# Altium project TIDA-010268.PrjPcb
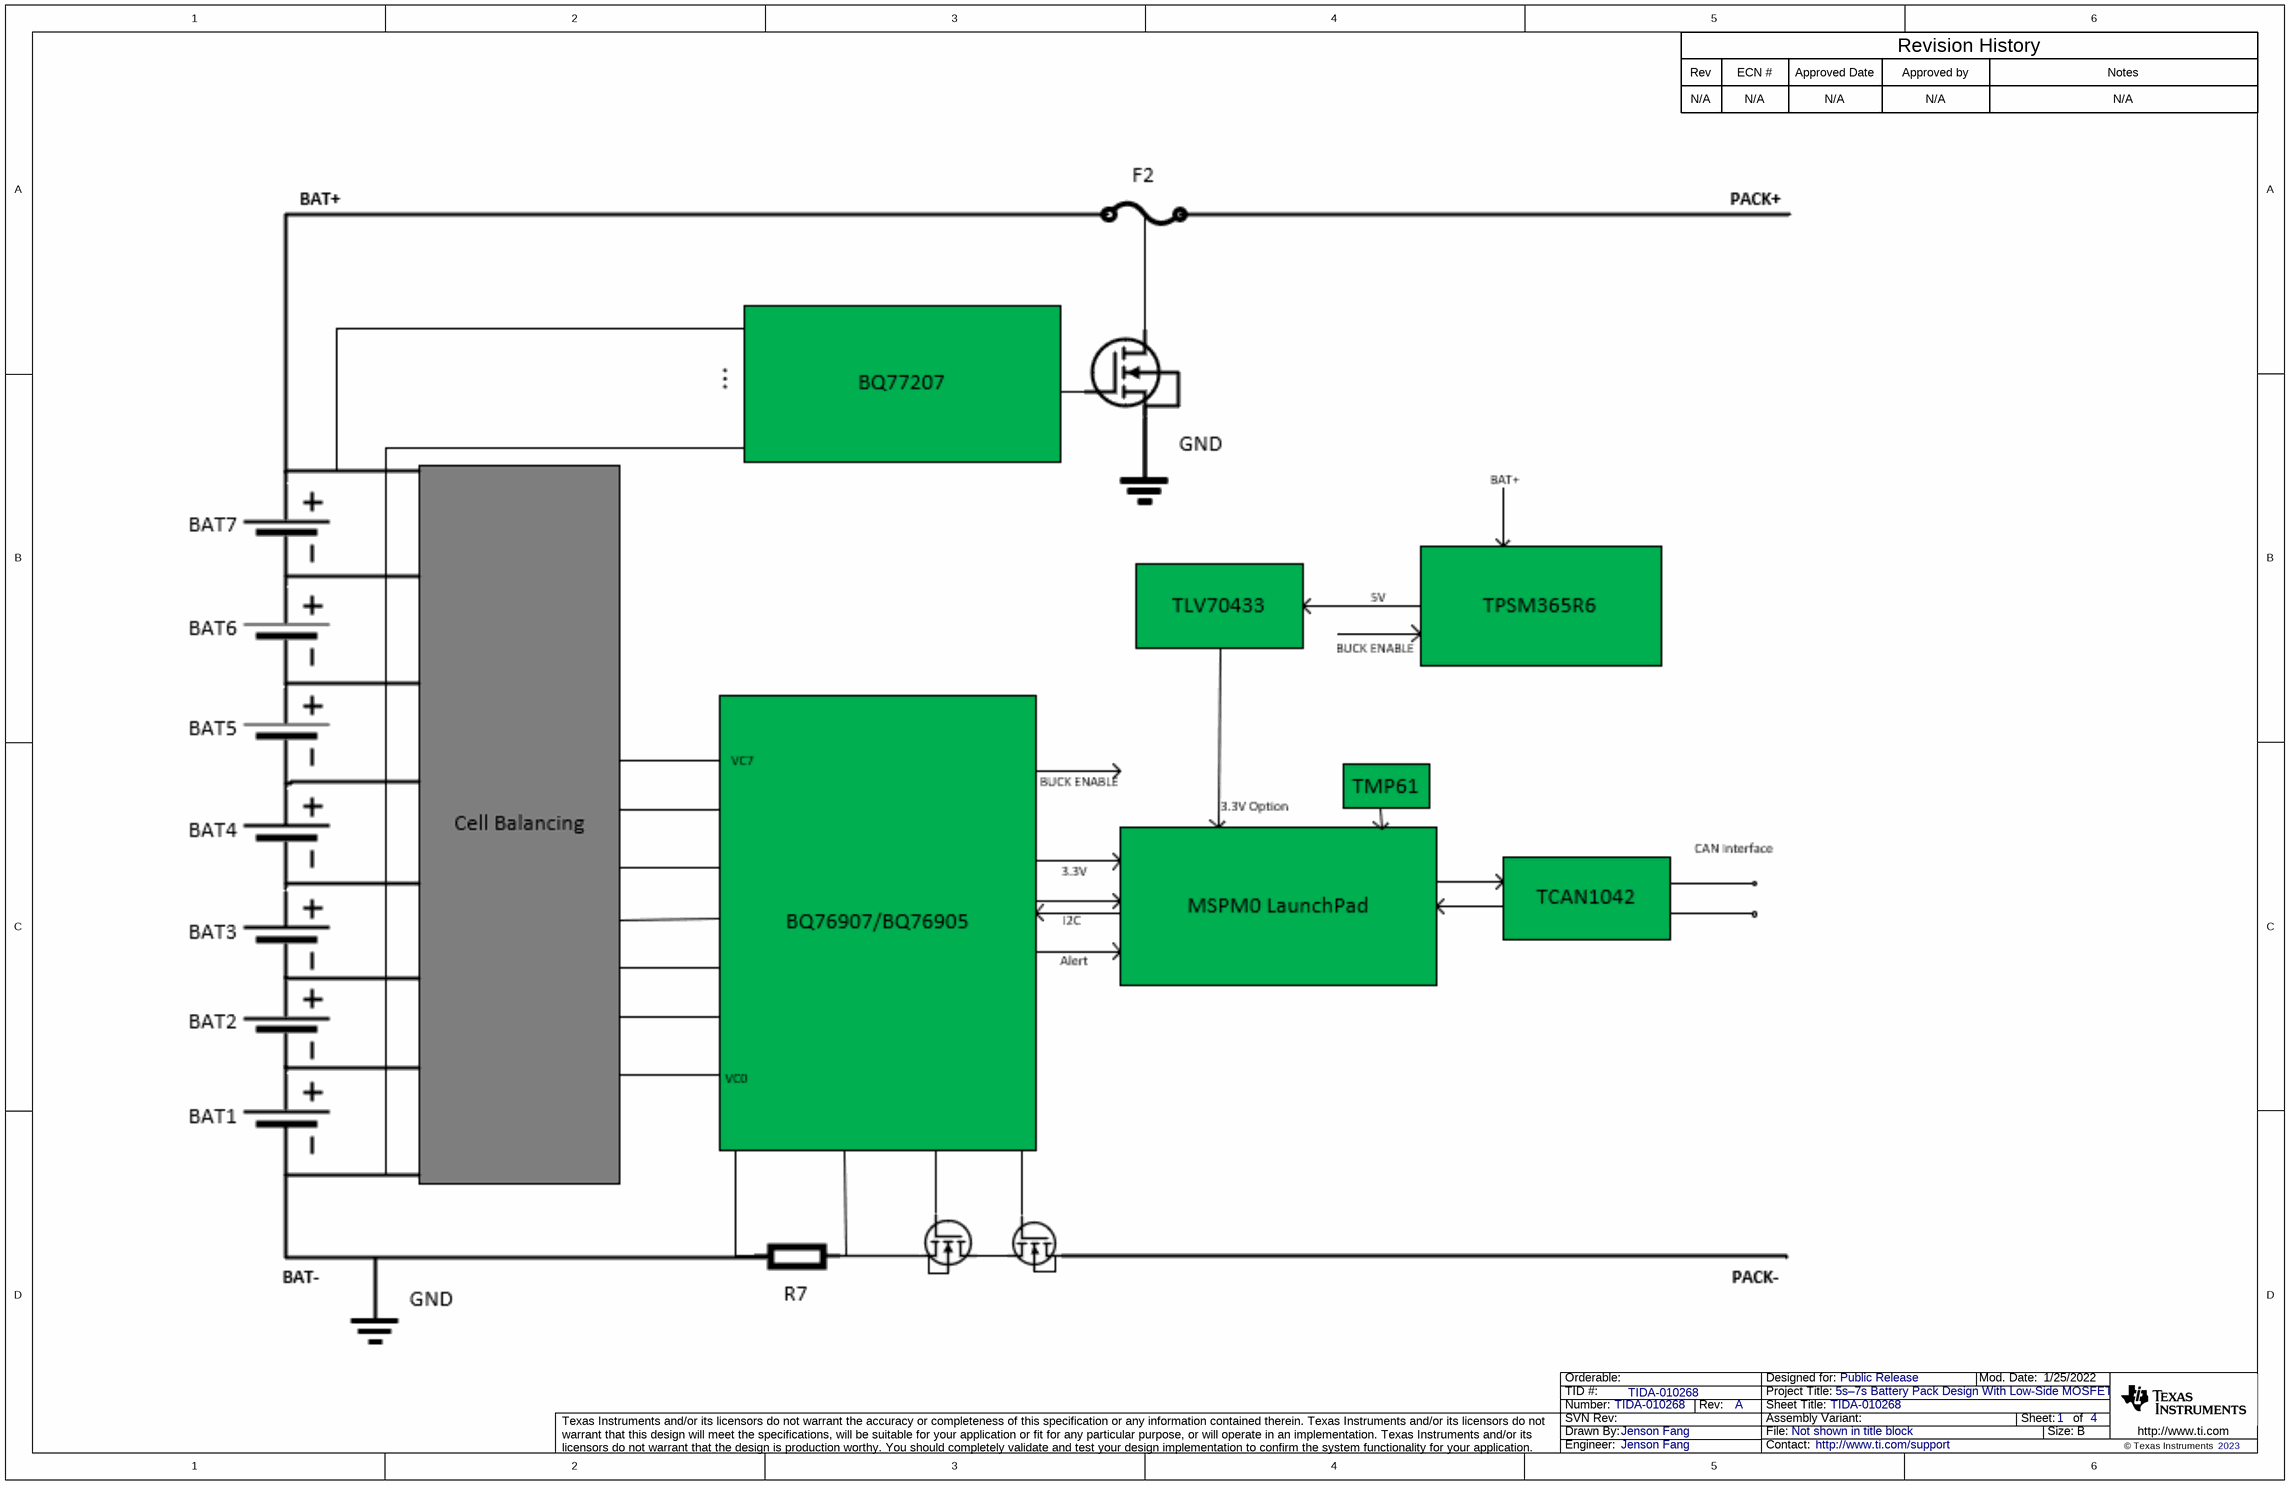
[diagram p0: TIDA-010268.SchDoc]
CopyrightYear: 2023; PCB_Layout: Jenson Fang; PCB_Rev: A; PRJ_Customer: Public Release; PRJ_Engineer: Jenson Fang; PRJ_Number: TIDA-010268; PRJ_Title: 5s–7s Battery Pack Design With Low-Side MOSFET Control; SCH_Rev: A; TechSupport: http://www.ti.com/support; TID: TIDA-010268
4 sheets, 155 parts. Net scope: global (net labels, ports and power ports of the same name join across sheets).
Board file: TIDA-010268.PcbDoc
Sheets:
  TIDA-010268.SchDoc
  TIDA-010268_Monitor and CB.SchDoc
  TIDA-010268_Power Rail.SchDoc
  TIDA-010268_Hardware.SchDoc

## Sheet TIDA-010268.SchDoc: TIDA-010268
size 431 x 279 mm; Date: Not shown in title block; ApprovedBy: Not shown in title block; CheckedBy: Not shown in title block; Author: Jenson Fang; CompanyName: Not shown in title block; DrawnBy: Jenson Fang; Engineer: Jenson Fang; Organization: Not shown in title block; Address1: Not shown in title block; Address2: Not shown in title block; Address3: Not shown in title block; Address4: Not shown in title block; DocumentNumber: 1; Revision: Use project parameter SCH_Rev; SheetNumber: 1; SheetTotal: 4; PageSetup: Record=PageOptions¦CenterHorizontal=True¦CenterVertical=True¦PrintScale=1.00¦XCorrection=1.00¦YCorrection=1.00¦PrintKind=0¦BorderSize=5000000¦LeftOffset=0¦BottomOffset=0¦Orientation=2¦PaperLength=1000¦PaperWidth=1000¦Scale=100¦PaperSource=15¦PrintQuality=600¦MediaType=1¦DitherType=10¦PaperKind=Letter¦PrintScaleMode=1

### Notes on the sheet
- Rev
- N/A
- ECN #
- Approved Date
- Approved by
- Revision History
- Notes

## Sheet TIDA-010268_Monitor and CB.SchDoc: TIDA-010268
size 431 x 279 mm; Date: Not shown in title block; ApprovedBy: Not shown in title block; CheckedBy: Not shown in title block; Author: Jenson Fang; CompanyName: Not shown in title block; DrawnBy: Jenson Fang; Engineer: Jenson Fang; Organization: Not shown in title block; Address1: Not shown in title block; Address2: Not shown in title block; Address3: Not shown in title block; Address4: Not shown in title block; DocumentNumber: 2; Revision: Use project parameter SCH_Rev; SheetNumber: 2; SheetTotal: 4; PageSetup: Record=PageOptions¦CenterHorizontal=True¦CenterVertical=True¦PrintScale=1.00¦XCorrection=1.00¦YCorrection=1.00¦PrintKind=0¦BorderSize=5000000¦LeftOffset=0¦BottomOffset=0¦Orientation=2¦PaperLength=1000¦PaperWidth=1000¦Scale=100¦PaperSource=15¦PrintQuality=600¦MediaType=1¦DitherType=10¦PaperKind=Letter¦PrintScaleMode=1
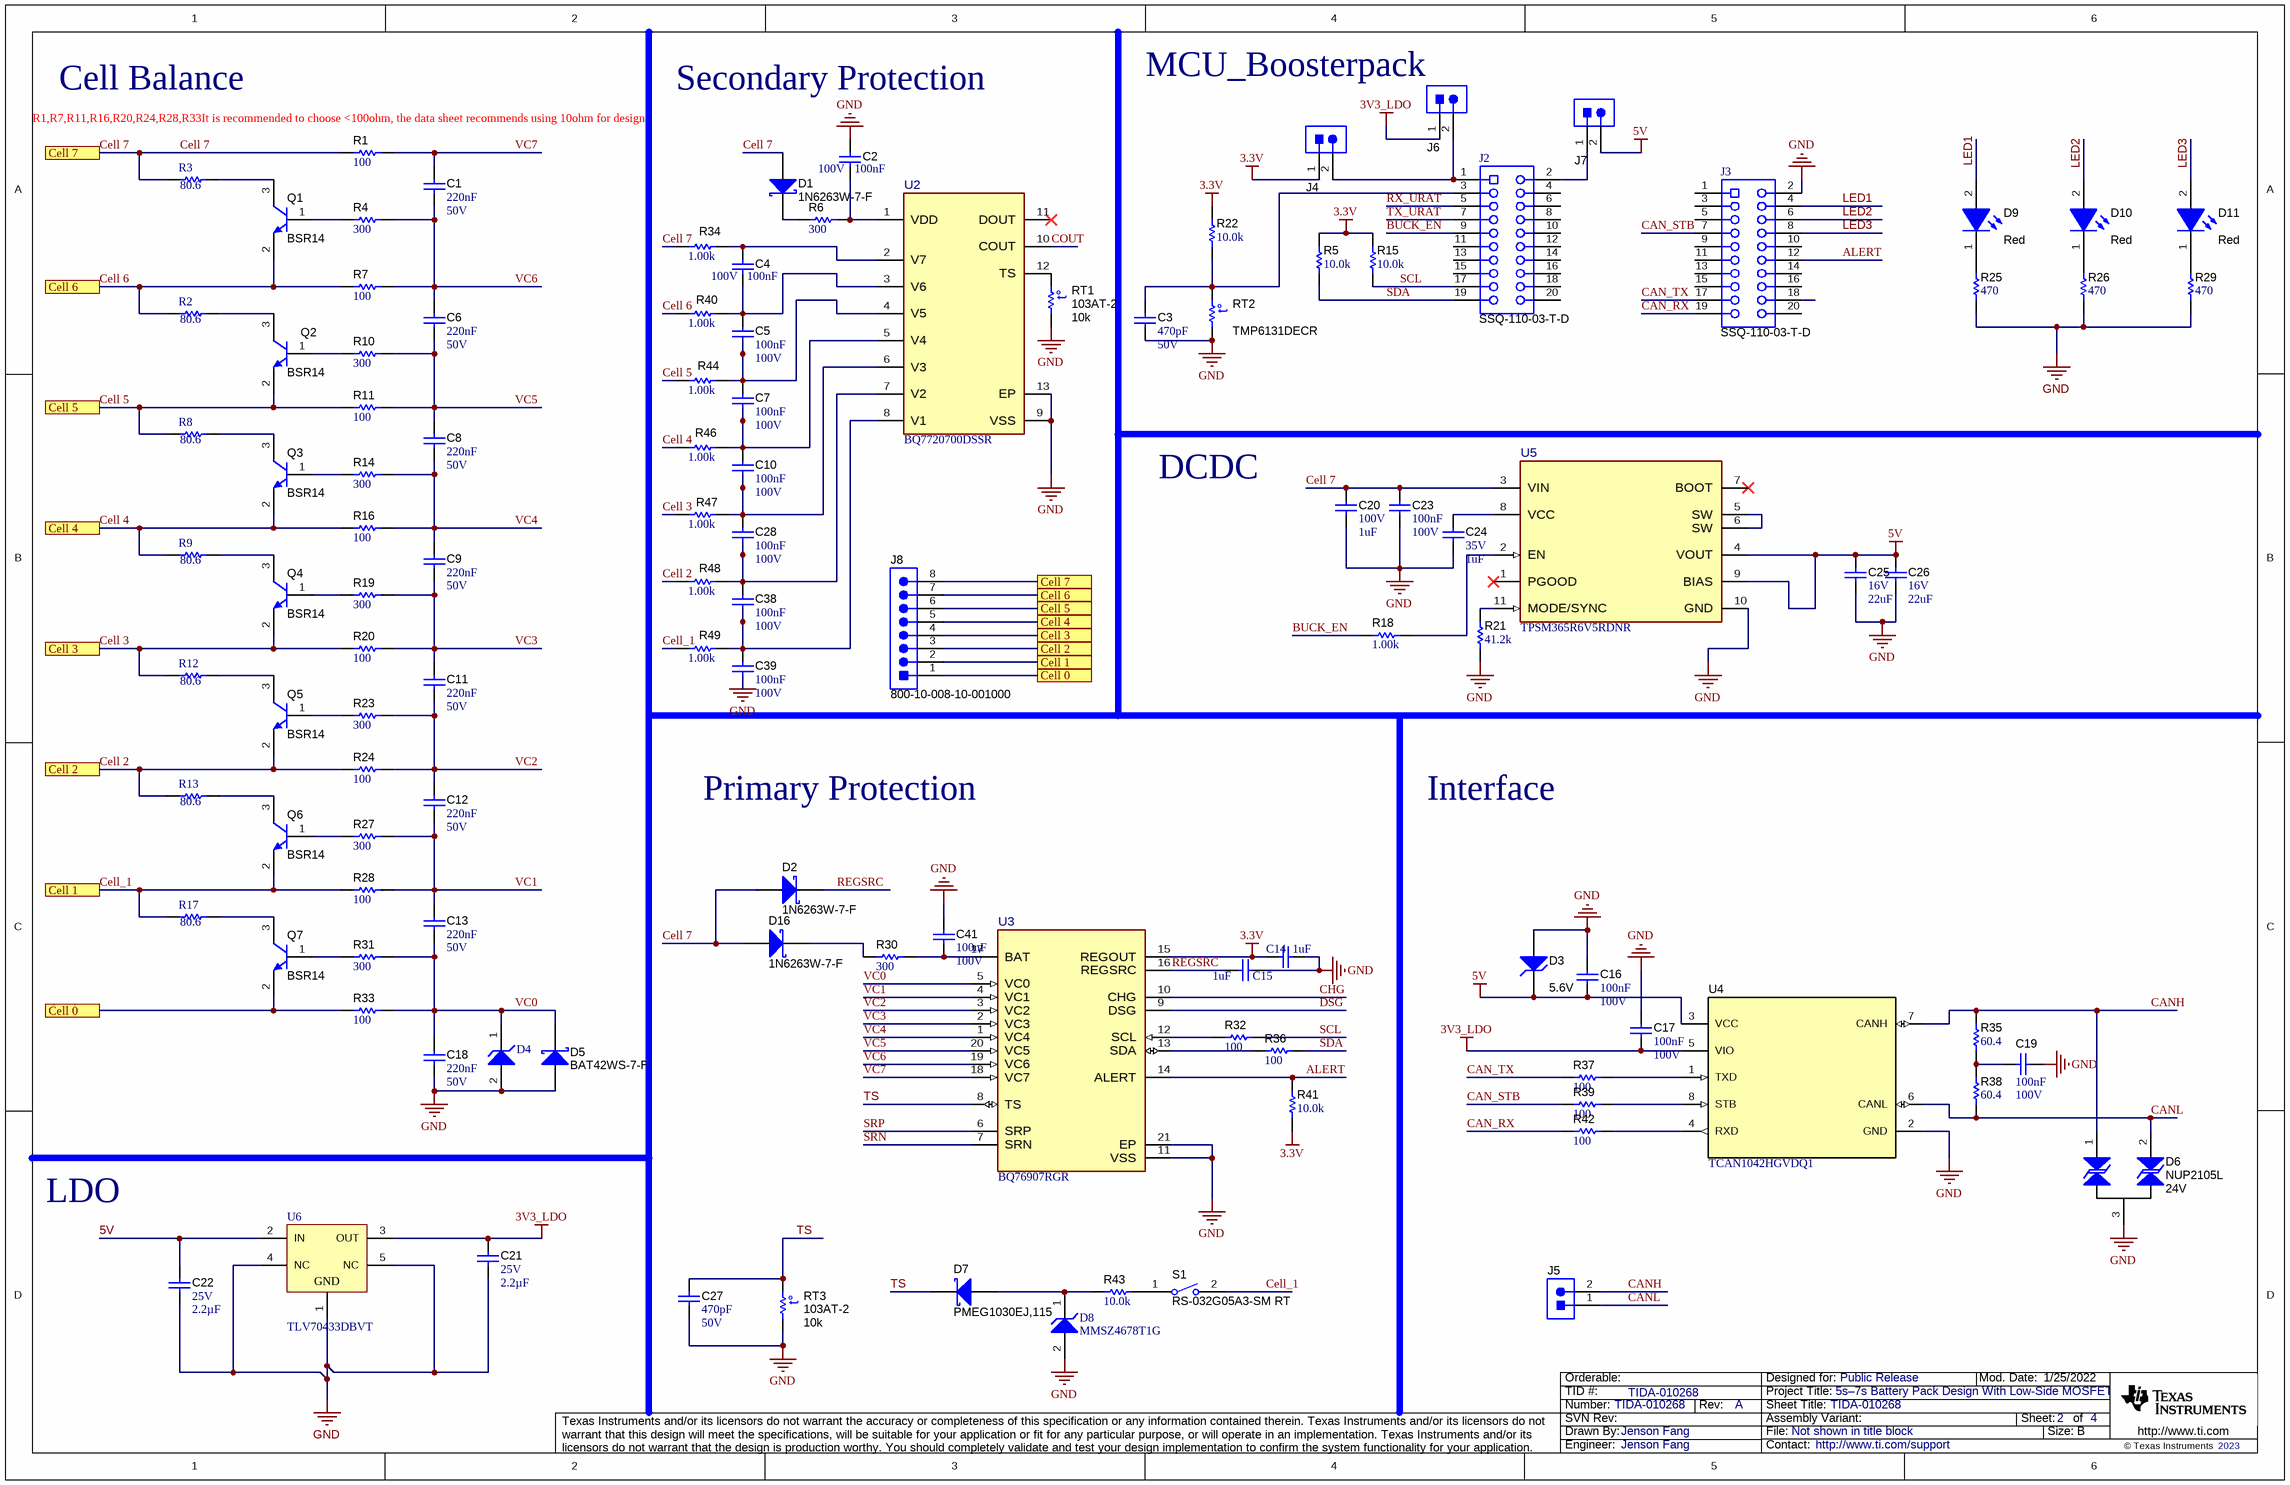
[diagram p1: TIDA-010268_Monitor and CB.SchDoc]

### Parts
C1  Cap_F: 220nF  VDC_V: 50V  [0603]  (hidden comment: GRM188R71H224KAC4D)
C2  Cap_F: 100nF  VDC_V: 100V  [0603]  (hidden comment: GRM188R72A104KA35J)
C3  Cap_F: 470pF  VDC_V: 50V  [0603]  (hidden comment: GRM188R71H471KA01D)
C4  Cap_F: 100nF  VDC_V: 100V  [0603]  (hidden comment: GRM188R72A104KA35J)
C5  Cap_F: 100nF  VDC_V: 100V  [0603]  (hidden comment: GRM188R72A104KA35J)
C6  Cap_F: 220nF  VDC_V: 50V  [0603]  (hidden comment: GRM188R71H224KAC4D)
C7  Cap_F: 100nF  VDC_V: 100V  [0603]  (hidden comment: GRM188R72A104KA35J)
C8  Cap_F: 220nF  VDC_V: 50V  [0603]  (hidden comment: GRM188R71H224KAC4D)
C9  Cap_F: 220nF  VDC_V: 50V  [0603]  (hidden comment: GRM188R71H224KAC4D)
C10  Cap_F: 100nF  VDC_V: 100V  [0603]  (hidden comment: GRM188R72A104KA35J)
C11  Cap_F: 220nF  VDC_V: 50V  [0603]  (hidden comment: GRM188R71H224KAC4D)
C12  Cap_F: 220nF  VDC_V: 50V  [0603]  (hidden comment: GRM188R71H224KAC4D)
C13  Cap_F: 220nF  VDC_V: 50V  [0603]  (hidden comment: GRM188R71H224KAC4D)
C14  value 1uF  [CAPC1608X90X35LL10T15]  (hidden comment: GRM188R61E105KA12D)
C15  value 1uF  [CAPC1608X90X35LL10T15]  (hidden comment: GRM188R61E105KA12D)
C16  Cap_F: 100nF  VDC_V: 100V  [0603]  (hidden comment: GRM188R72A104KA35J)
C17  Cap_F: 100nF  VDC_V: 100V  [0603]  (hidden comment: GRM188R72A104KA35J)
C18  Cap_F: 220nF  VDC_V: 50V  [0603]  (hidden comment: GRM188R71H224KAC4D)
C19  Cap_F: 100nF  VDC_V: 100V  [0603]  (hidden comment: GRM188R72A104KA35J)
C20  VDC_V: 100V  ValueDisplayed: 1uF  [1210_180]  (hidden comment: GRM32CR72A105KA35L)
C21  VDC_V: 25V  ValueDisplayed: 2.2µF  [0603]  (hidden comment: GRM188C71E225KE11D)
C22  VDC_V: 25V  ValueDisplayed: 2.2µF  [0603]  (hidden comment: GRM188C71E225KE11D)
C23  Cap_F: 100nF  VDC_V: 100V  [0603]  (hidden comment: GRM188R72A104KA35J)
C24  VDC_V: 35V  ValueDisplayed: 1uF  [0402]  (hidden comment: GRM155R6YA105KE11D)
C25  VDC_V: 16V  ValueDisplayed: 22uF  [0805_HV]  (hidden comment: GRM21BC81C226ME44L)
C26  VDC_V: 16V  ValueDisplayed: 22uF  [0805_HV]  (hidden comment: GRM21BC81C226ME44L)
C27  Cap_F: 470pF  VDC_V: 50V  [0603]  (hidden comment: GRM188R71H471KA01D)
C28  Cap_F: 100nF  VDC_V: 100V  [0603]  (hidden comment: GRM188R72A104KA35J)
C38  Cap_F: 100nF  VDC_V: 100V  [0603]  (hidden comment: GRM188R72A104KA35J)
C39  Cap_F: 100nF  VDC_V: 100V  [0603]  (hidden comment: GRM188R72A104KA35J)
C41  Cap_F: 100nF  VDC_V: 100V  [0603]  (hidden comment: GRM188R72A104KA35J)
D1  1N6263W-7-F  [SOD-123]
D2  1N6263W-7-F  [SOD-123]
D3  value 5.6V  [SOD-123]  (hidden comment: MMSZ4690T1G)
D4  MMSZ4685T1G  [ONSC-SOD-123-2-425-04_V]  (value not drawn)
D5  BAT42WS-7-F  [SOD-323]
D6  NUP2105L  value 24V  [SOT-23]
D7  PMEG1030EJ,115  [SOD-323F]
D8  MMSZ4678T1G  [ONSC-SOD-123-2-425-04_V]
D9  value Red  [WL_SMCW_RED_1206]  (hidden comment: 150120RS75000)
D10  value Red  [WL_SMCW_RED_1206]  (hidden comment: 150120RS75000)
D11  value Red  [WL_SMCW_RED_1206]  (hidden comment: 150120RS75000)
D16  1N6263W-7-F  [SOD-123]
J2  SSQ-110-03-T-D  [Samtec_SSQ-110-03-x-D]
J3  SSQ-110-03-T-D  [Samtec_SSQ-110-03-x-D]
J4  61300211121  [WURTH_61300211121]  (value not drawn)
J5  61300211121  [WURTH_61300211121]  (value not drawn)
J6  61300211121  [WURTH_61300211121]  (value not drawn)
J7  61300211121  [WURTH_61300211121]  (value not drawn)
J8  800-10-008-10-001000  [Mill-Max_800-10-008-10-001000]
Q1  BSR14  [SOT-23]
Q2  BSR14  [SOT-23]
Q3  BSR14  [SOT-23]
Q4  BSR14  [SOT-23]
Q5  BSR14  [SOT-23]
Q6  BSR14  [SOT-23]
Q7  BSR14  [SOT-23]
R1  ValueDisplayed: 100  [0603]  (hidden comment: CRCW0603100RFKEA)
R2  vaule: 80.6  [RESC3216X60X45LL10T20]  (hidden comment: CRCW120680R6FKEA)
R3  vaule: 80.6  [RESC3216X60X45LL10T20]  (hidden comment: CRCW120680R6FKEA)
R4  ValueDisplayed: 300  [0603]  (hidden comment: CRCW0603300RJNEA)
R5  ValueDisplayed: 10.0k  [0603]  (hidden comment: CRCW060310K0FKEA)
R6  ValueDisplayed: 300  [0603]  (hidden comment: CRCW0603300RJNEA)
R7  ValueDisplayed: 100  [0603]  (hidden comment: CRCW0603100RFKEA)
R8  vaule: 80.6  [RESC3216X60X45LL10T20]  (hidden comment: CRCW120680R6FKEA)
R9  vaule: 80.6  [RESC3216X60X45LL10T20]  (hidden comment: CRCW120680R6FKEA)
R10  ValueDisplayed: 300  [0603]  (hidden comment: CRCW0603300RJNEA)
R11  ValueDisplayed: 100  [0603]  (hidden comment: CRCW0603100RFKEA)
R12  vaule: 80.6  [RESC3216X60X45LL10T20]  (hidden comment: CRCW120680R6FKEA)
R13  vaule: 80.6  [RESC3216X60X45LL10T20]  (hidden comment: CRCW120680R6FKEA)
R14  ValueDisplayed: 300  [0603]  (hidden comment: CRCW0603300RJNEA)
R15  ValueDisplayed: 10.0k  [0603]  (hidden comment: CRCW060310K0FKEA)
R16  ValueDisplayed: 100  [0603]  (hidden comment: CRCW0603100RFKEA)
R17  vaule: 80.6  [RESC3216X60X45LL10T20]  (hidden comment: CRCW120680R6FKEA)
R18  ValueDisplayed: 1.00k  [0603]  (hidden comment: CRCW06031K00FKEA)
R19  ValueDisplayed: 300  [0603]  (hidden comment: CRCW0603300RJNEA)
R20  ValueDisplayed: 100  [0603]  (hidden comment: CRCW0603100RFKEA)
R21  ValueDisplayed: 41.2k  [0402]  (hidden comment: CRCW040241K2FKED)
R22  ValueDisplayed: 10.0k  [0603]  (hidden comment: CRCW060310K0FKEA)
R23  ValueDisplayed: 300  [0603]  (hidden comment: CRCW0603300RJNEA)
R24  ValueDisplayed: 100  [0603]  (hidden comment: CRCW0603100RFKEA)
R25  ValueDisplayed: 470  [0603]  (hidden comment: CRCW0603470RJNEA)
R26  ValueDisplayed: 470  [0603]  (hidden comment: CRCW0603470RJNEA)
R27  ValueDisplayed: 300  [0603]  (hidden comment: CRCW0603300RJNEA)
R28  ValueDisplayed: 100  [0603]  (hidden comment: CRCW0603100RFKEA)
R29  ValueDisplayed: 470  [0603]  (hidden comment: CRCW0603470RJNEA)
R30  ValueDisplayed: 300  [0603]  (hidden comment: CRCW0603300RJNEA)
R31  ValueDisplayed: 300  [0603]  (hidden comment: CRCW0603300RJNEA)
R32  ValueDisplayed: 100  [0603]  (hidden comment: CRCW0603100RJNEA)
R33  ValueDisplayed: 100  [0603]  (hidden comment: CRCW0603100RFKEA)
R34  ValueDisplayed: 1.00k  [0603]  (hidden comment: CRCW06031K00FKEA)
R35  ValueDisplayed: 60.4  [0603]  (hidden comment: CRCW060360R4FKEA)
R36  ValueDisplayed: 100  [0603]  (hidden comment: CRCW0603100RJNEA)
R37  ValueDisplayed: 100  [0603]  (hidden comment: CRCW0603100RJNEA)
R38  ValueDisplayed: 60.4  [0603]  (hidden comment: CRCW060360R4FKEA)
R39  ValueDisplayed: 100  [0603]  (hidden comment: CRCW0603100RJNEA)
R40  ValueDisplayed: 1.00k  [0603]  (hidden comment: CRCW06031K00FKEA)
R41  ValueDisplayed: 10.0k  [0603]  (hidden comment: CRCW060310K0FKEA)
R42  ValueDisplayed: 100  [0603]  (hidden comment: CRCW0603100RJNEA)
R43  ValueDisplayed: 10.0k  [0603]  (hidden comment: CRCW060310K0FKEA)
R44  ValueDisplayed: 1.00k  [0603]  (hidden comment: CRCW06031K00FKEA)
R46  ValueDisplayed: 1.00k  [0603]  (hidden comment: CRCW06031K00FKEA)
R47  ValueDisplayed: 1.00k  [0603]  (hidden comment: CRCW06031K00FKEA)
R48  ValueDisplayed: 1.00k  [0603]  (hidden comment: CRCW06031K00FKEA)
R49  ValueDisplayed: 1.00k  [0603]  (hidden comment: CRCW06031K00FKEA)
RT1  103AT-2  value 10k  [THERMISTOR_103AT-2]
RT2  TMP6131DECR  [DEC0002A]
RT3  103AT-2  value 10k  [THERMISTOR_103AT-2]
S1  RS-032G05A3-SM RT  [SW_RS-032G05A3-SM]
U2  BQ7720700DSSR  [DSS0012B-MFG]
U3  BQ76907RGR  [RGR0020A-MFG]
U4  TCAN1042HGVDQ1  [D0008A_L]
U5  TPSM365R6V5RDNR  [RDN0011A-MFG]
U6  TLV70433DBVT  [DBV0005A_N]

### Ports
Cell 0, Cell 1, Cell 2, Cell 3, Cell 4, Cell 5, Cell 6, Cell 7

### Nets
3.3V: C14.2 J4.1 R5.2 R15.2 R22.2 R41.1 U3.15(REGOUT)
3V3_LDO: C17.2 C21.1 J6.1 U4.5(VIO) U6.3(OUT)
5V: C16.2 C22.1 C25.1 C26.1 D3.1(K) J7.2 U4.3(VCC) U5.4(VOUT) U5.9(BIAS) U6.2(IN)
GND: C2.1 C3.2 C14.1 C15.2 C16.1 C17.1 C18.2 C19.2 C20.2 C21.2 C22.2 C23.2 C24.2 C25.2 C26.2 C27.2 C39.2 C41.1 D3.2(A) D4.2(A) D5.2(A) D6.3 D8.2(A) J3.2 R21.1 R25.1 R26.1 R29.1 RT1.1 RT2.1 RT3.1 U2.9(VSS) U2.13(EP) U3.11(VSS) U3.21(EP) U4.2(GND) U5.10(GND) U6.1(GND) U6.4(NC) U6.5(NC)
ALERT: J3.12 R41.2 U3.14(ALERT)
BUCK_EN: J2.9 R18.1
CAN_RX: J3.19 R42.1
CAN_STB: J3.7 R39.1
CAN_TX: J3.17 R37.1
CANH: D6.1 J5.2 R35.2 U4.7(CANH)
CANL: D6.2 J5.1 R38.1 U4.6(CANL)
Cell 0: J8.1 Q7.2(E) R33.1 ; port Cell 0
Cell 2: J8.3 Q5.2(E) R13.1 R24.1 R48.1 ; port Cell 2
Cell 3: J8.4 Q4.2(E) R12.1 R20.1 R47.1 ; port Cell 3
Cell 4: J8.5 Q3.2(E) R9.1 R16.1 R46.1 ; port Cell 4
Cell 5: J8.6 Q2.2(E) R8.1 R11.1 R44.1 ; port Cell 5
Cell 6: J8.7 Q1.2(E) R2.1 R7.1 R40.1 ; port Cell 6
Cell 7: C20.1 C23.1 D1.2(A) D2.2(A) D16.2(A) J8.8 R1.1 R3.1 R34.1 U5.3(VIN) ; port Cell 7
Cell_1: J8.2 Q6.2(E) R17.1 R28.1 R49.1 S1.2 ; port Cell 1
CHG: U3.10(CHG)
COUT: U2.10(COUT)
DSG: U3.9(DSG)
LED1: D9.2(A) J3.4
LED2: D10.2(A) J3.6
LED3: D11.2(A) J3.8
REGSRC: C15.1 D2.1(K) U3.16(REGSRC)
RX_URAT: J2.5
SCL: J2.17 R15.1 R32.2
SDA: J2.19 R5.1 R36.2
SRN: U3.7(SRN)
SRP: U3.6(SRP)
TS: C27.1 D7.1(K) RT3.2 U3.8(TS)
TX_URAT: J2.7
VC0: C13.2 C18.1 D4.1(K) D5.1(K) R31.2 R33.2 U3.5(VC0)
VC1: C12.2 C13.1 R27.2 R28.2 U3.4(VC1)
VC2: C11.2 C12.1 R23.2 R24.2 U3.3(VC2)
VC3: C9.2 C11.1 R19.2 R20.2 U3.2(VC3)
VC4: C8.2 C9.1 R14.2 R16.2 U3.1(VC4)
VC5: C6.2 C8.1 R10.2 R11.2 U3.20(VC5)
VC6: C1.2 C6.1 R4.2 R7.2 U3.19(VC6)
VC7: C1.1 R1.2 U3.18(VC7)
NetC2_2: C2.2 R6.2 U2.1(VDD)
NetC3_1: C3.1 J2.3 R22.1 RT2.2
NetC4_1: C4.1 R34.2 U2.2(V7)
NetC4_2: C4.2 C5.1 R40.2 U2.3(V6)
NetC5_2: C5.2 C7.1 R44.2 U2.4(V5)
NetC7_2: C7.2 C10.1 R46.2 U2.5(V4)
NetC10_2: C10.2 C28.1 R47.2 U2.6(V3)
NetC19_1: C19.1 R35.1 R38.2
NetC24_1: C24.1 U5.8(VCC)
NetC28_2: C28.2 C38.1 R48.2 U2.7(V2)
NetC38_2: C38.2 C39.1 R49.2 U2.8(V1)
NetC41_2: C41.2 R30.2 U3.17(BAT)
NetD1_1: D1.1(K) R6.1
NetD7_2: D7.2(A) D8.1(K) R43.2
NetD9_1: D9.1(K) R25.2
NetD10_1: D10.1(K) R26.2
NetD11_1: D11.1(K) R29.2
NetD16_1: D16.1(K) R30.1
NetJ2_1: J2.1 J4.2 J6.2
NetJ2_2: J2.2 J7.1
NetQ1_1: Q1.1(B) R4.1
NetQ1_3: Q1.3(C) R3.2
NetQ2_1: Q2.1(B) R10.1
NetQ2_3: Q2.3(C) R2.2
NetQ3_1: Q3.1(B) R14.1
NetQ3_3: Q3.3(C) R8.2
NetQ4_1: Q4.1(B) R19.1
NetQ4_3: Q4.3(C) R9.2
NetQ5_1: Q5.1(B) R23.1
NetQ5_3: Q5.3(C) R12.2
NetQ6_1: Q6.1(B) R27.1
NetQ6_3: Q6.3(C) R13.2
NetQ7_1: Q7.1(B) R31.1
NetQ7_3: Q7.3(C) R17.2
NetR18_2: R18.2 U5.2(EN)
NetR21_2: R21.2 U5.11(MODE/SYNC)
NetR32_1: R32.1 U3.12(SCL)
NetR36_1: R36.1 U3.13(SDA)
NetR37_2: R37.2 U4.1(TXD)
NetR39_2: R39.2 U4.8(STB)
NetR42_2: R42.2 U4.4(RXD)
NetR43_1: R43.1 S1.1
NetRT1_2: RT1.2 U2.12(TS)
NetU5_5: U5.5(SW) U5.6(SW)

Not connected (* = marked no-connect by the designer): J2 4 6 8 10 11 12 13 14 15 16 18 20; J3 1 3 5 9 10 11 13 14 15 16 18 20; U2 11(DOUT)*; U5 1(PGOOD)* 7(BOOT)*

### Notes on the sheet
- Cell Balance
- Secondary Protection
- (near J6) MCU_Boosterpack
- (near R1) R1,R7,R11,R16,R20,R24,R28,R33It is recommended to choose <100ohm, the data sheet recommends using 10ohm for design
- DCDC
- Primary Protection
- Interface
- LDO

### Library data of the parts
C1 C6 C8 C9 C11-C13 C18 = CMP-0007445-2: CAP, CERM, 0.22 uF, 50 V, +/- 10%, X7R, 0603; Manufacturer: MuRata; TaMin_C: -55°C; Polarized: N; SizeAreaWB_mm2: 4.68; Value1: Unknown; U/M: EA; Value: 0.22uF; TaMax_C: 125°C; SizeZ_mm: 1; SizeX_mm: 1.6; SizeY_mm: 0.8; SizeArea_mm2: 1.28; AEC Category: Q200
C2 C4 C5 C7 C10 C16 C17 C19 C23 C28 C38 C39 C41 = CMP-0007470-5: CAP, CERM, 0.1 uF, 100 V, +/- 10%, X7R, 0603; Manufacturer: MuRata; TaMin_C: -55°C; Polarized: N; SizeAreaWB_mm2: 4.68; Value1: Unknown; U/M: EA; Value: 0.1uF; TaMax_C: 125°C; SizeZ_mm: 1; SizeX_mm: 1.6; SizeY_mm: 0.8; SizeArea_mm2: 1.28; AEC Category: Q200
C3 C27 = CMP-0007455-4: CAP, CERM, 470 pF, 50 V, +/- 10%, X7R, 0603; Manufacturer: MuRata; TaMin_C: -55°C; Polarized: N; SizeAreaWB_mm2: 4.68; Value1: Unknown; U/M: EA; Value: 470pF; TaMax_C: 125°C; SizeZ_mm: 1; SizeX_mm: 1.6; SizeY_mm: 0.8; SizeArea_mm2: 1.28; AEC Category: Q200
C14 C15 = CMP-2006-02459-1: 1uF,25V; Manufacturer: Murata
C20 = CMP-0009180-2: CAP, CERM, 1 uF, 100 V, +/- 10%, X7R, 1210; Manufacturer: MuRata; TaMin_C: -55°C; Polarized: N; SizeAreaWB_mm2: 14.7; Value1: Unknown; U/M: EA; Value: 1uF; TaMax_C: 125°C; SizeZ_mm: 1.8; SizeX_mm: 3.2; SizeY_mm: 2.5; Cap_Case: 1210; SizeArea_mm2: 8; Cap_F: 1µF; AEC Category: Q200
C21 C22 = CMP-0075366-3: CAP, CERM, 2.2 µF, 25 V,+/- 10%, X7S, 0603; Manufacturer: MuRata; TaMin_C: -55°C; Polarized: N; SizeAreaWB_mm2: 4.68; U/M: EA; Value: 2.2uF; TaMax_C: 125°C; SizeZ_mm: 1.0; SizeX_mm: 1.6; SizeY_mm: 0.8; SizeArea_mm2: 1.28; AEC Category: Q200
C24 = CMP-0006619-1: CAP, CERM, 1 uF, 35 V, +/- 10%, X5R, 0402; Manufacturer: MuRata; TaMin_C: -55°C; Polarized: N; SizeAreaWB_mm2: 3; Value1: Unknown; U/M: EA; Value: 1uF; TaMax_C: 85°C; SizeZ_mm: 0.6; SizeX_mm: 1; SizeY_mm: 0.5; Cap_F: 1µF; AEC Category: Q200
C25 C26 = CMP-0008269-1: CAP, CERM, 22 uF, 16 V, +/- 20%, X6S, 0805; Manufacturer: MuRata; TaMin_C: -55°C; Polarized: N; SizeAreaWB_mm2: 6.75; Value1: Unknown; U/M: EA; Value: 22uF; TaMax_C: 105°C; SizeZ_mm: 1.45; SizeX_mm: 2; SizeY_mm: 1.25; Cap_Case: 0805; SizeArea_mm2: 2.5; Cap_F: 22µF; AEC Category: Q200
D1 D2 D16 = CMP-0028361-2: Diode, Schottky, 60 V, 0.015 A, SOD-123; Manufacturer: Diodes Inc.; Value: 60V; Green_REACh: Incomplete; Value1: 0.015A; Io_A: 15mA; SizeAreaWB_mm2: 13.095; AEC Category: Q101; Vf_V: 800mV; SizeZ_mm: 1.35; SizeX_mm: 3.85; SizeArea_mm2: 6.545; Value2: 0.8V; Green_Lifecycle: Not Set; SizeY_mm: 1.7
D3 = CMP-0005787-1: Diode, Zener, 5.6 V, 500 mW, SOD-123; Manufacturer: ON Semiconductor; Power_W: 500mW; SizeAreaWB_mm2: 13.095; Value1: 0.5W; RJA_CperW: 340; U/M: EA; SizeZ_mm: 1.35; SizeX_mm: 3.85; SizeY_mm: 1.7; SizeArea_mm2: 6.545; AEC Category: Q101
D4 = CMP-1060-00574-1: Zener Voltage Regulator  3.6v, 500 mW, 2-Pin SOD-123, Pb-Free, Tape and Reel; Manufacturer: On Semiconductor; VZ Typ (V): 3.6; P Max (W): 0.5
D5 = CMP-0028447-2: Diode, Schottky, 30 V, 0.2 A, SOD-323; Manufacturer: Diodes Inc.; SizeZ_mm: 1; AEC Category: Q101; Green_REACh: Incomplete; Green_Lifecycle: Not Set; Vr_V: 30V; Vf_V: 1V; Io_A: 200mA; SizeY_mm: 1.35; Value1: 0.2A; Value: 30V; SizeArea_mm2: 3.645; SizeX_mm: 2.7; SizeAreaWB_mm2: 8.695
D6 = CMP-0005919-3: Diode, TVS, Bi, 24 V, SOT-23; Manufacturer: ON Semiconductor; PartNumber: NUP2105LT1G; Value1: 350W; SizeAreaWB_mm2: 14; SizeY_mm: 3; SizeZ_mm: 1.1; SizeX_mm: 2.5; AEC Category: Q101; SizeArea_mm2: 7.5
D7 = CMP-0028852-1: Diode, Schottky, 10 V, 3 A, SOD-323F; Manufacturer: Nexperia; Io_A: 3A; Green_Lifecycle: Not Set; SizeAreaWB_mm2: 7.875; Vr_V: 10V; Green_REACh: Incomplete; TJmax_C: 150°C; U/M: EA; Value: 10V; SizeZ_mm: 0.8; SizeX_mm: 2.5; SizeY_mm: 1.25; Vf_V: 530mV; Value2: 0.53V; SizeArea_mm2: 3.125; AEC Qualified: N; AEC Category: Q101
D8 = CMP-1060-00511-1: Zener Voltage Regulator, 500 mW, 2-Pin SOD-123, Pb-Free, Tape and Reel; Manufacturer: On Semiconductor; P Max (W): 0.5; VZ Typ (V): 1.8
D9-D11 = CMP-0002935-1: LED, Red, SMD; Manufacturer: Wurth Elektronik; Io_A: 20mA; Power_TotalModule: 72mW; Vr_V: 5V; Tjmax_C: 85°C; Value1: 0.072W; U/M: EA; Angle: 140; Ir_A: 10µA; Vf_V: 2V; Type: AlInGaP
J2 J3 = CMP-0079854-1: Receptacle, 2.54mm, 10x2, Tin, TH; Manufacturer: Samtec; Cert_VDE: N; Current_A: 6.3A; Green_Lifecycle: Active; Gender: Female; Cert_CSA: Y; Green_REACh: Incomplete; Voltage_V: 550V; CompType: Socket Strip; Row_Count: 2; RowSpacing_mm: 2.54
J4-J7 = CMP-0054794-2: Header, 2.54 mm, 2x1, Gold, TH; Manufacturer: Wurth Elektronik; Shrouded: N; Gender: Male; Green_REACh: Passed; Pitch_mm: 2.54; Green_Lifecycle: Active; Row_Count: 1; Cert_UL: Y
J8 = CMP-0055090-1: Header, 100mil, 8x1, TH; Manufacturer: Mill-Max; CT: FALSE; CNHeader: TRUE
Q1-Q7 = CMP-0000433-1: Transistor, NPN, 40 V, 0.8 A, SOT-23; Manufacturer: NXP Semiconductor; TaMax_C: 150°C; Value2: 300; Value1: 0.8 A; Vcesat1_V: 300mV; SizeX_mm: 2.5; SizeY_mm: 3; TaMin_C: -65°C; IcRated_A: 800mA; CompType: BJT; SizeZ_mm: 1.1; Value: 40 V; SizeArea_mm2: 7.5; NPN: 1; Vceo_V: 40V; PNP: 0; AEC Category: Q101; SizeAreaWB_mm2: 14; U/M: EA
R1 R7 R11 R16 R20 R24 R28 R33 = CMP-0021991-3: RES, 100, 1%, 0.1 W, 0603; Manufacturer: Vishay-Dale; Power_W: 100mW; TempCo: 100 ppm/C; Value_Code: 100R; U/M: EA; Value: 100; EIA_Code: E96; SizeX_mm: 1.6; SizeY_mm: 0.8; SizeZ_mm: 1; Value2: 0.1W; SizeArea_mm2: 1.28; VDC_V: 75V; AEC Category: Q200
R2 R3 R8 R9 R12 R13 R17 = CMP-2003-02397-1: RES, 80.6, 1%, 0.25 W, 1206; Manufacturer: Vishay Dale
R4 R10 R14 R19 R23 R27 R31 = CMP-0025781-1: RES, 300, 5%, 0.1 W, 0603; Manufacturer: Vishay-Dale; Power_W: 100mW; TempCo: 200 ppm/C; Value_Code: 300R; U/M: EA; Value: 300; EIA_Code: E24; SizeX_mm: 1.6; SizeY_mm: 0.8; SizeZ_mm: 1; Value2: 0.1W; SizeArea_mm2: 1.28; VDC_V: 75V; AEC Category: Q200
R5 R15 R22 R41 R43 = CMP-0021998-4: RES, 10.0 k, 1%, 0.1 W, AEC-Q200 Grade 0, 0603; Manufacturer: Vishay-Dale; Power_W: 100mW; TempCo: 100 ppm/C; Value_Code: 10k0; Value: 10.0k; EIA_Code: E96; Res_ohm: 10k; SizeX_mm: 1.6; SizeY_mm: 0.8; SizeZ_mm: 1; Value2: 0.1W; SizeArea_mm2: 1.28; AEC Qualified: Y; VDC_V: 75V; AEC Category: Q200; AEC Grade: 0
R6 R30 = CMP-0025781-3: RES, 300, 5%, 0.1 W, 0603; Manufacturer: Vishay-Dale; Power_W: 100mW; TempCo: 200 ppm/C; Value_Code: 300R; U/M: EA; Value: 300; EIA_Code: E24; SizeX_mm: 1.6; SizeY_mm: 0.8; SizeZ_mm: 1; Value2: 0.1W; SizeArea_mm2: 1.28; VDC_V: 75V; AEC Category: Q200
R18 R34 R40 R44 R46-R49 = CMP-0022109-5: RES, 1.00 k, 1%, 0.1 W, AEC-Q200 Grade 0, 0603; Manufacturer: Vishay-Dale; Power_W: 100mW; TempCo: 100 ppm/C; Value_Code: 1k00; Value: 1.00k; EIA_Code: E96; Res_ohm: 1k; SizeX_mm: 1.6; SizeY_mm: 0.8; SizeZ_mm: 1; Value2: 0.1W; SizeArea_mm2: 1.28; AEC Qualified: Y; VDC_V: 75V; AEC Category: Q200; AEC Grade: 0
R21 = CMP-0026371-2: RES, 41.2 k, 1%, 0.063 W, AEC-Q200 Grade 0, 0402; Manufacturer: Vishay-Dale; Power_W: 63mW; TempCo: 100 ppm/C; Value_Code: 41k2; Value: 41.2k; EIA_Code: E96; SizeX_mm: 1; SizeY_mm: 0.5; SizeZ_mm: 0.6; Value2: 0.063W; AEC Qualified: Y; VDC_V: 50V; AEC Category: Q200; AEC Grade: 0
R25 R26 R29 = CMP-0025813-4: RES, 470, 5%, 0.1 W, AEC-Q200 Grade 0, 0603; Manufacturer: Vishay-Dale; Power_W: 100mW; TempCo: 200 ppm/C; Value_Code: 470R; Value: 470; EIA_Code: E24; SizeX_mm: 1.6; SizeY_mm: 0.8; SizeZ_mm: 1; Value2: 0.1W; SizeArea_mm2: 1.28; AEC Qualified: Y; VDC_V: 75V; AEC Category: Q200; AEC Grade: 0
R32 R36 R37 R39 R42 = CMP-0025700-4: RES, 100, 5%, 0.1 W, AEC-Q200 Grade 0, 0603; Manufacturer: Vishay-Dale; Power_W: 100mW; TempCo: 200 ppm/C; Value_Code: 100R; Value: 100; EIA_Code: E24; SizeX_mm: 1.6; SizeY_mm: 0.8; SizeZ_mm: 1; Value2: 0.1W; SizeArea_mm2: 1.28; AEC Qualified: Y; VDC_V: 75V; AEC Category: Q200; AEC Grade: 0
R35 R38 = CMP-0022533-4: RES, 60.4, 1%, 0.1 W, AEC-Q200 Grade 0, 0603; Manufacturer: Vishay-Dale; Power_W: 100mW; TempCo: 100 ppm/C; Value_Code: 60R4; Value: 60.4; EIA_Code: E96; SizeX_mm: 1.6; SizeY_mm: 0.8; SizeZ_mm: 1; Value2: 0.1W; SizeArea_mm2: 1.28; AEC Qualified: Y; VDC_V: 75V; AEC Category: Q200; AEC Grade: 0
RT1 RT3 = CMP-0002341-2: Thermistor NTC, 10.0k ohm, 1%, Disc, 5x8.4 mm; Manufacturer: SEMITEC Corporation; TaMax_C: 110°C; TaMin_C: -50°C; Power_W: 10mW; U/M: EA
RT2 = CMP-0084566-1: Thermistor, DEC0002A (X1SON-2); Alternate Manufacturer: Texas Instruments; Alternate PartNumber: TMP6131DECT; CompType: IC; AEC Category: Q200; SizeX_mm: 1; AEC Qualified: N; SizeZ_mm: 0.5; SizeArea_mm2: 0.6; SizeAreaWB_mm2: 3.2
S1 = CMP-0002210-1: Switch, Tactile, SPST-NO, 0.05A, 12V, SMD; Manufacturer: C&K Components; CurrentRating_mA: 50A; PositionCount: 1; SwitchFunction: Off-Mom
U2 = CMP-0092221-1: Voltage and Temperature Protection for 3-Series to 7-Series Cell Li-Ion Batteries with Internal Delay Timer; Manufacturer: Texas Instruments; AEC Qualified: No; Min Supply Voltage: 5V; Nominal Supply Current: 2uA; Max Supply Voltage: 38.5V; Number Of Outputs: 1; Number Of Cells: 7; SizeZ_mm: 0.8mm; TJmax_C: +150°C; TaMax_C: +85°C; Standoff Height: 0mm; TaMin_C: -40°C
U3 = CMP-0091326-1: 2-s to 7-s High Accuracy Battery Monitor and Protector for Li-Ion, LiPolymer, and LiFePO4  Battery Packs; Manufacturer: Texas Instruments; Nominal Supply Current: 120uA; Output Voltage: 38.5V; Number Of Outputs: 1; AEC Qualified: No; SizeZ_mm: 1mm; Number Of Cells: 7; Min Supply Voltage: 3V; TJmax_C: +150°C; Standoff Height: 0mm
U4 = CMP-0075992-1: Automotive Fault Protected CAN Transceiver With Flexible Data-Rate, D0008A (SOIC-8); Manufacturer: Texas Instruments; Alternate PartNumber: TCAN1042HGVDRQ1; SizeAreaWB_mm2: 56.58; SizeArea_mm2: 30.38; SizeZ_mm: 1.75; SizeY_mm: 6.2; U/M: EA; CompType: IC; SizeX_mm: 4.9
U5 = CMP-0098344-1: 3-V to 65-V Input, 1-V to 13-V Output, 600-mA Synchronous Buck Converter Power Module in a HotRod QFN Package; Manufacturer: Texas Instruments; SizeZ_mm: 2.1mm; AEC Qualified: No; Max Duty Cycle: 98%; Max Supply Voltage: 65V; Min Supply Voltage: 3.6V; Number Of Outputs: 1; Output Type: Fixed; Output Voltage: 5V; Standoff Height: 0mm; Switching Frequency: 1MHz; TJmax_C: +125°C
U6 = CMP-0035592-1: Single Output LDO, 150 mA, Fixed 3.3 V Output, 2.5 to 24 V Input, with Ultra-Low IQ, 5-pin SOT-23 (DBV), -40 to 125 degC, Green (RoHS & no Sb/Br); Manufacturer: Texas Instruments; Fixed Output Options(V): 3.3; Vin(Max)(V): 24; Vin(Min)(V): 2.5; SubFamily: Single Channel LDO; Vdo(Typ)(mV): 400; Accuracy(%): 2; Iq(Typ)(mA): 0.003; Iout(Max)(A): 0.15

## Sheet TIDA-010268_Power Rail.SchDoc: TIDA-010268
size 431 x 279 mm; Date: Not shown in title block; ApprovedBy: Not shown in title block; CheckedBy: Not shown in title block; Author: Jenson Fang; CompanyName: Not shown in title block; DrawnBy: Jenson Fang; Engineer: Jenson Fang; Organization: Not shown in title block; Address1: Not shown in title block; Address2: Not shown in title block; Address3: Not shown in title block; Address4: Not shown in title block; DocumentNumber: 1; Revision: Use project parameter SCH_Rev; SheetNumber: 3; SheetTotal: 4; PageSetup: Record=PageOptions¦CenterHorizontal=True¦CenterVertical=True¦PrintScale=1.00¦XCorrection=1.00¦YCorrection=1.00¦PrintKind=0¦BorderSize=5000000¦LeftOffset=0¦BottomOffset=0¦Orientation=2¦PaperLength=1000¦PaperWidth=1000¦Scale=100¦PaperSource=15¦PrintQuality=600¦MediaType=1¦DitherType=10¦PaperKind=Letter¦PrintScaleMode=1
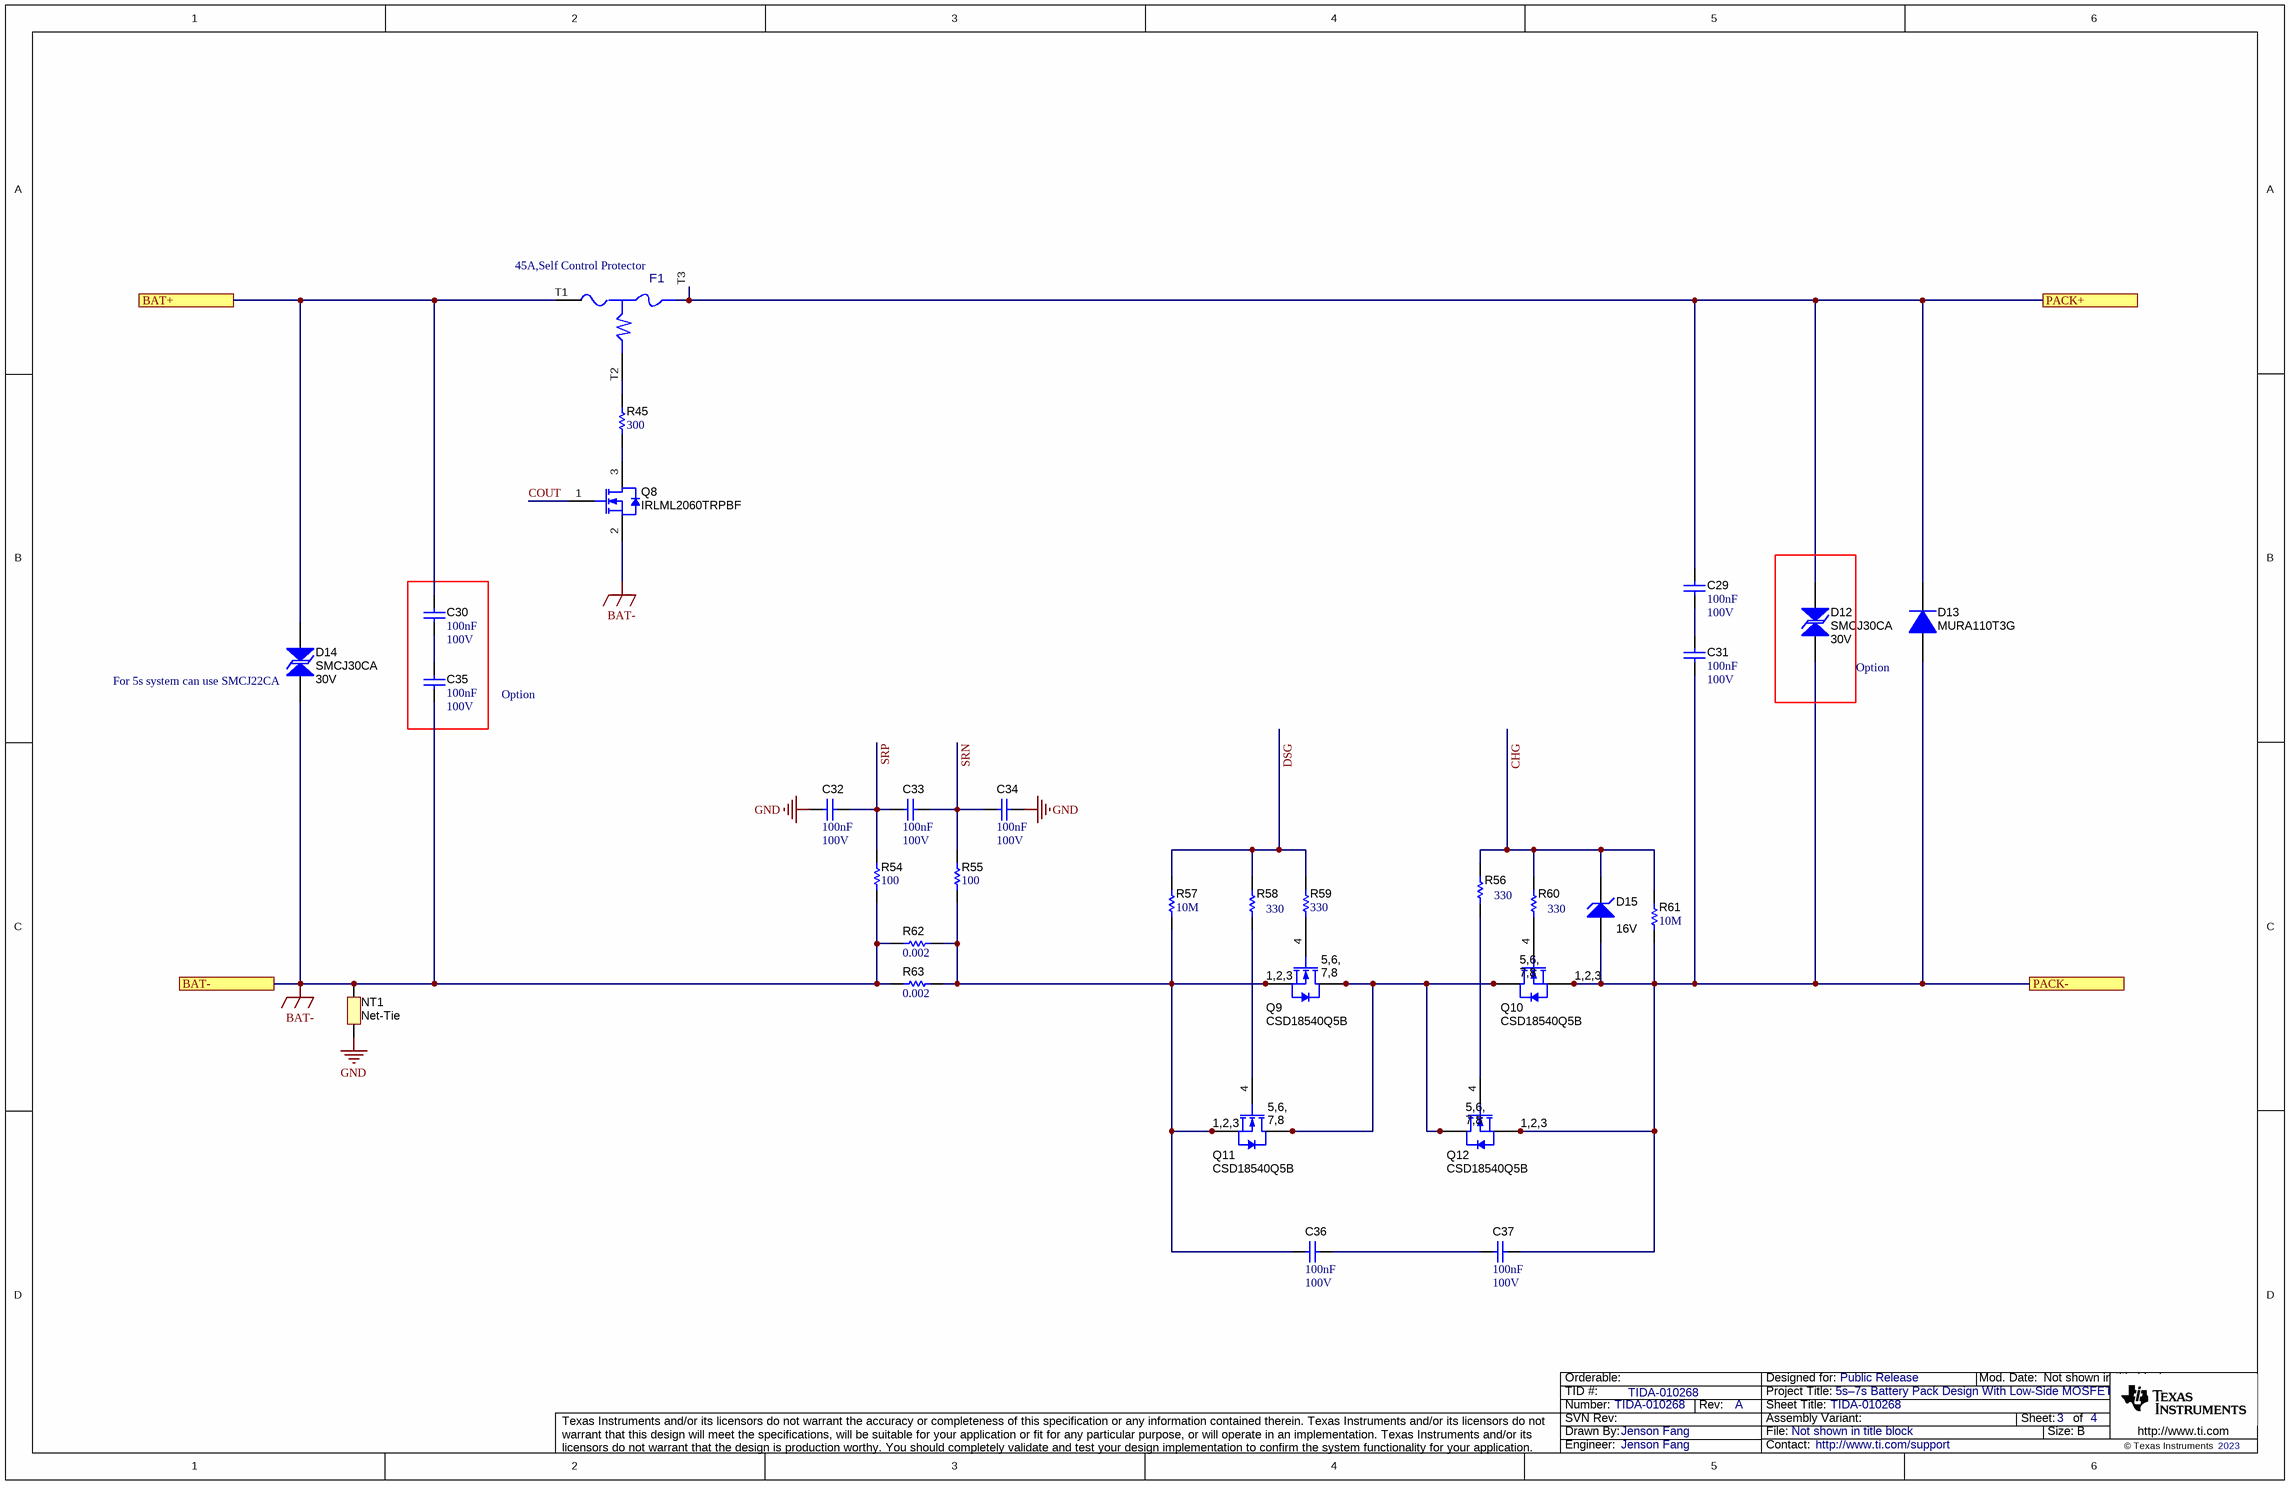
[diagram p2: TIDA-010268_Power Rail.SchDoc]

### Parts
C29  Cap_F: 100nF  VDC_V: 100V  [0603]  (hidden comment: GRM188R72A104KA35J)
C30  Cap_F: 100nF  VDC_V: 100V  [0603]  (hidden comment: GRM188R72A104KA35J)
C31  Cap_F: 100nF  VDC_V: 100V  [0603]  (hidden comment: GRM188R72A104KA35J)
C32  Cap_F: 100nF  VDC_V: 100V  [0603]  (hidden comment: GRM188R72A104KA35J)
C33  Cap_F: 100nF  VDC_V: 100V  [0603]  (hidden comment: GRM188R72A104KA35J)
C34  Cap_F: 100nF  VDC_V: 100V  [0603]  (hidden comment: GRM188R72A104KA35J)
C35  Cap_F: 100nF  VDC_V: 100V  [0603]  (hidden comment: GRM188R72A104KA35J)
C36  Cap_F: 100nF  VDC_V: 100V  [0603]  (hidden comment: GRM188R72A104KA35J)
C37  Cap_F: 100nF  VDC_V: 100V  [0603]  (hidden comment: GRM188R72A104KA35J)
D12  SMCJ30CA  value 30V  [SMC_Bi]
D13  MURA110T3G  [SMA]
D14  SMCJ30CA  value 30V  [SMC_Bi]
D15  value 16V  [SOD-123]  (hidden comment: MMSZ5246B-7-F)
F1  SFK-3045  [FP-SFK-3045_FUSE, SMT-MFG]  (value not drawn)
NT1  Net-Tie  [Net-Tie_0805_HV_NoOverlay]  (net tie, no BOM)
Q8  IRLML2060TRPBF  [SOT-23]
Q9  CSD18540Q5B  [DNK0008A]
Q10  CSD18540Q5B  [DNK0008A]
Q11  CSD18540Q5B  [DNK0008A]
Q12  CSD18540Q5B  [DNK0008A]
R45  ValueDisplayed: 300  [0603]  (hidden comment: CRCW0603300RJNEA)
R54  ValueDisplayed: 100  [0603]  (hidden comment: CRCW0603100RFKEA)
R55  ValueDisplayed: 100  [0603]  (hidden comment: CRCW0603100RFKEA)
R56  ValueDisplayed: 330  [0603]  (hidden comment: CRCW0603330RJNEA)
R57  ValueDisplayed: 10M  [0603]  (hidden comment: CRCW060310M0JNEA)
R58  ValueDisplayed: 330  [0603]  (hidden comment: CRCW0603330RJNEA)
R59  ValueDisplayed: 330  [0603]  (hidden comment: CRCW0603330RJNEA)
R60  ValueDisplayed: 330  [0603]  (hidden comment: CRCW0603330RJNEA)
R61  ValueDisplayed: 10M  [0603]  (hidden comment: CRCW060310M0JNEA)
R62  ValueDisplayed: 0.002  [2512]  (hidden comment: CSNL2512FT2L00)
R63  ValueDisplayed: 0.002  [2512]  (hidden comment: CSNL2512FT2L00)

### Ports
BAT+, BAT-, PACK+, PACK-

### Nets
BAT-: C35.2 D14.1 NT1.2 Q8.2(S) R54.1 R62.1 R63.1 ; port BAT-
GND: C32.1 C34.2 NT1.1
BAT+: C30.1 D14.2 F1.T1 ; port BAT+
CHG: D15.1(K) R56.2 R60.2 R61.2
COUT: Q8.1(G)
DSG: R57.2 R58.2 R59.2
PACK+: C29.1 D12.2 D13.1(K) F1.T3 ; port PACK+
PACK-: C31.2 C37.2 D12.1 D13.2(A) D15.2(A) Q10.1(S) Q10.2(S) Q10.3(S) Q12.1(S) Q12.2(S) Q12.3(S) R61.1 ; port PACK-
SRN: C33.2 C34.1 R55.1
SRP: C32.2 C33.1 R54.2
NetC29_2: C29.2 C31.1
NetC30_2: C30.2 C35.1
NetC36_1: C36.1 Q9.1(S) Q9.2(S) Q9.3(S) Q11.1(S) Q11.2(S) Q11.3(S) R55.2 R57.1 R62.2 R63.2
NetC36_2: C36.2 C37.1
NetF1_T2: F1.T2 R45.2
NetQ8_3: Q8.3(D) R45.1
NetQ9_4: Q9.4(G) R59.1
NetQ9_5: Q9.5(D) Q9.6(D) Q9.7(D) Q9.8(D) Q9.9(D) Q10.5(D) Q10.6(D) Q10.7(D) Q10.8(D) Q10.9(D) Q11.5(D) Q11.6(D) Q11.7(D) Q11.8(D) Q11.9(D) Q12.5(D) Q12.6(D) Q12.7(D) Q12.8(D) Q12.9(D)
NetQ10_4: Q10.4(G) R60.1
NetQ11_4: Q11.4(G) R58.1
NetQ12_4: Q12.4(G) R56.1

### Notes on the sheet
- (near F1) 45A,Self Control Protector
- (near D14) For 5s system can use SMCJ22CA
- Option

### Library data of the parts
C29-C37 = CMP-0007470-5: as C2 on sheet TIDA-010268_Monitor and CB
D12 D14 = CMP-0005692-3: Diode, TVS, Bi, 30 V, 48.4 Vc, SMC; Manufacturer: Littelfuse; Vbr_Min: 33.3V; AEC Category: Q101; Vc: 48.4V; RJA_CperW: 75; SizeZ_mm: 2.6; Ipp: 31A; SizeAreaWB_mm2: 83.2686; AEC Qualified: N; Vbr_Max: 36.8V; Value1: 1500W; Ppk: 1.5kW; SizeX_mm: 8.13; SizeArea_mm2: 50.5686; SizeY_mm: 6.22
D13 = CMP-0029196-2: Diode, Ultrafast, 100 V, 2 A, SMA; Manufacturer: ON Semiconductor; SizeX_mm: 5.59; TJmax_C: 175°C; SizeAreaWB_mm2: 37.3428; Io_A: 2A; Green_REACh: Passed; SizeY_mm: 2.92; Value: 100V; Green_Lifecycle: Active; AEC Qualified: N; SizeArea_mm2: 16.3228; AEC Category: Q101; SizeZ_mm: 2.87
D15 = CMP-0005754-3: Diode, Zener, 16 V, 500 mW, SOD-123; Manufacturer: Diodes Inc.; RJA_CperW: 350; Power_W: 500mW; Value1: 0.5W; SizeZ_mm: 1.35; SizeY_mm: 1.7; SizeX_mm: 3.85; SizeAreaWB_mm2: 13.095; AEC Category: Q101; SizeArea_mm2: 6.545
F1 = CMP-0086786-1: Fuse, Self Control Protector, 45A, 6 to 7 cells, SMD; Manufacturer: Dexerials; SizeZ_mm: 2mm
NT1 = CMP-0078142-5: Single point connection between nets.
Q8 = CMP-0000848-1: MOSFET, N-CH, 60 V, 1.2 A, SOT-23; Alternate Manufacturer: None; Manufacturer: International Rectifier; SizeZ_mm: 1.1; ChType: N; Value2: 0.67 nC; Value1: 0.6; VdsMax_V: 60V; SizeX_mm: 2.5; SizeY_mm: 3; Vgs_V: 16V; Value: 60V; Rdson45_ohm: 0.64; SizeArea_mm2: 7.5; AEC Category: Q101; IdsMax_A: 1.2A; SizeAreaWB_mm2: 14; U/M: EA; QgTyp_nC: 0.67
Q9-Q12 = CMP-0000823-2: MOSFET, N-CH, 60 V, 100 A, DNK0008A (VSON-CLIP-8); Alternate Manufacturer: None; Manufacturer: Texas Instruments; SizeZ_mm: 1; ChType: N; Value2: 41 nC; Value1: 0.003; VdsMax_V: 60V; SizeX_mm: 6; SizeY_mm: 5; Vgs_V: 20V; Value: 60V; Rdson45_ohm: 3.3m; SizeArea_mm2: 30; AEC Category: Q101; IdsMax_A: 100A; SizeAreaWB_mm2: 56; U/M: EA; QgTyp_nC: 41
R45 = CMP-0025781-3: as R6 on sheet TIDA-010268_Monitor and CB
R54 R55 = CMP-0021991-2: RES, 100, 1%, 0.1 W, 0603; Manufacturer: Vishay-Dale; Power_W: 100mW; TempCo: 100 ppm/C; Value_Code: 100R; U/M: EA; Value: 100; EIA_Code: E96; SizeX_mm: 1.6; SizeY_mm: 0.8; SizeZ_mm: 1; Value2: 0.1W; SizeArea_mm2: 1.28; VDC_V: 75V; AEC Category: Q200
R56 R58-R60 = CMP-0025785-3: RES, 330, 5%, 0.1 W, 0603; Manufacturer: Vishay-Dale; Power_W: 100mW; TempCo: 200 ppm/C; Value_Code: 330R; U/M: EA; Value: 330; EIA_Code: E24; SizeX_mm: 1.6; SizeY_mm: 0.8; SizeZ_mm: 1; Value2: 0.1W; SizeArea_mm2: 1.28; VDC_V: 75V; AEC Category: Q200
R57 R61 = CMP-0025702-2: RES, 10 M, 5%, 0.1 W, 0603; Manufacturer: Vishay-Dale; Power_W: 100mW; TempCo: 200 ppm/C; Value_Code: 10M0; U/M: EA; Value: 10Meg; EIA_Code: E24; SizeX_mm: 1.6; SizeY_mm: 0.8; SizeZ_mm: 1; Value2: 0.1W; SizeArea_mm2: 1.28; VDC_V: 75V; AEC Category: Q200
R62 R63 = CMP-0015756-2: RES, 0.002, 1%, 2 W, 2512; Manufacturer: Stackpole Electronics Inc; Power_W: 2W; TempCo: 50 ppm/C; Value_Code: 2L000; U/M: EA; Value: 0.002; Res_ohm: 2m; SizeX_mm: 6.3; SizeY_mm: 3.2; SizeZ_mm: 0.71; SizeArea_mm2: 20.16; VDC_V: 200V; AEC Category: Q200

## Sheet TIDA-010268_Hardware.SchDoc: TIDA-010268
size 431 x 279 mm; Date: Not shown in title block; ApprovedBy: Not shown in title block; CheckedBy: Not shown in title block; Author: Jenson Fang; CompanyName: Not shown in title block; DrawnBy: Jenson Fang; Engineer: Jenson Fang; Organization: Not shown in title block; Address1: Not shown in title block; Address2: Not shown in title block; Address3: Not shown in title block; Address4: Not shown in title block; DocumentNumber: 3; Revision: Use project parameter SCH_Rev; SheetNumber: 4; SheetTotal: 4; PageSetup: Record=PageOptions¦CenterHorizontal=True¦CenterVertical=True¦PrintScale=1.00¦XCorrection=1.00¦YCorrection=1.00¦PrintKind=0¦BorderSize=5000000¦LeftOffset=0¦BottomOffset=0¦Orientation=2¦PaperLength=1000¦PaperWidth=1000¦Scale=100¦PaperSource=15¦PrintQuality=600¦MediaType=1¦DitherType=10¦PaperKind=Letter¦PrintScaleMode=1
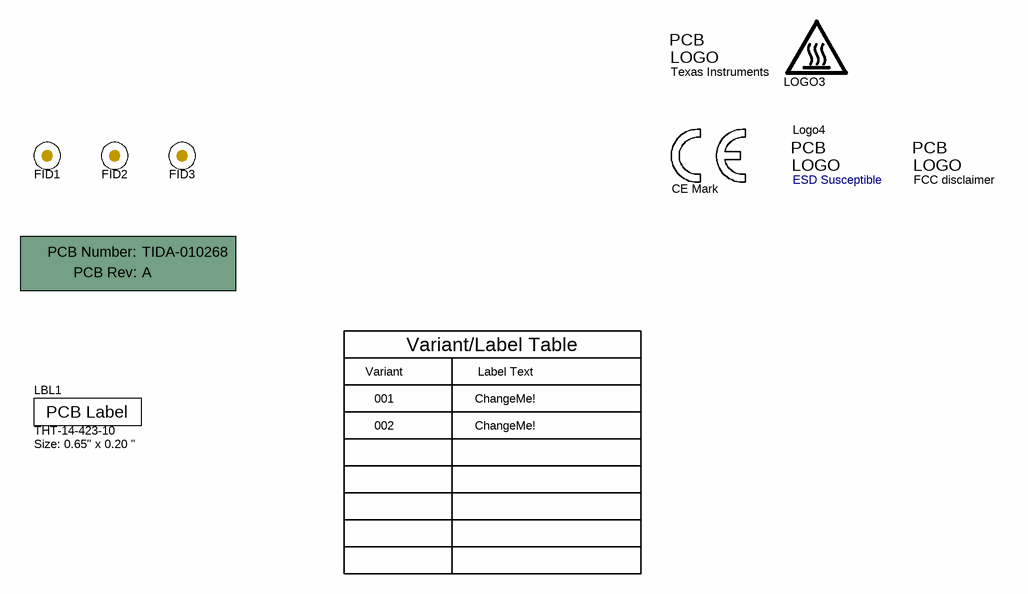
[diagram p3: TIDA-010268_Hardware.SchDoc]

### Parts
!PCB  Printed Circuit Board  (value not drawn)  (mechanical)
FID1  Fiducial  [Fiducial10-20]  (value not drawn)
FID2  Fiducial  [Fiducial10-20]  (value not drawn)
FID3  Fiducial  [Fiducial10-20]  (value not drawn)
LBL1  THT-14-423-10  Note: Size: 0.65" x 0.20 "  [Label_650x200]
Logo1  Texas Instruments  [TI_Stacked_Overlay_Small_Vertical]  (no BOM)
Logo2  CE Mark  [CE_Mark_5mm]  (no BOM)
LOGO3  CAUTION HOT SURFACE  [IEC_HotSurface_small]  (value not drawn)  (no BOM)
Logo4  ESD Susceptible  [ESD_Overlay_Small]  (no BOM)
Logo5  FCC disclaimer  [FCC_disclaimer]  (no BOM)

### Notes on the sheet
- Variant
- Variant/Label Table
- Label Text
- 001
- 002
- ChangeMe!

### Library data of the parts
!PCB = CMP-0003618-2: Manufacturer: Any; PartNumber: TIDA-010268
FID1-FID3 = CMP-0077181-1: Fiducial mark.  There is nothing to buy or mount.
LBL1 = CMP-0003625-1: Thermal Transfer Printable Labels, 0.650" W x 0.200" H - 10,000 per roll; Manufacturer: Brady; CompType: Label
Logo1 = CMP-0074838-1: Texas Instrument Corporate Signature; SymbolCreator: a0412235; Lib Reference: TI_Logo; Library Reference: Logo
Logo2 = CMP-0074844-1: SymbolCreator: a0412235
LOGO3 = IEC_HotSurface: IEC 61010-1 Hot Surface Warning; SymbolCreator: a0412235
Logo4 = CMP-0074840-1: ESD Susceptible Symbol; SymbolCreator: a0412235; Lib Reference: ESD_Susceptible
Logo5 = CMP-0074847-1: FCC_disclaimer; Library Reference: Logo

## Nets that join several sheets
GND: TIDA-010268_Monitor and CB (40 pins), TIDA-010268_Power Rail (C32.1 C34.2 NT1.1)
CHG: TIDA-010268_Monitor and CB (U3.10), TIDA-010268_Power Rail (D15.1 R56.2 R60.2 R61.2)
COUT: TIDA-010268_Monitor and CB (U2.10), TIDA-010268_Power Rail (Q8.1)
DSG: TIDA-010268_Monitor and CB (U3.9), TIDA-010268_Power Rail (R57.2 R58.2 R59.2)
SRN: TIDA-010268_Monitor and CB (U3.7), TIDA-010268_Power Rail (C33.2 C34.1 R55.1)
SRP: TIDA-010268_Monitor and CB (U3.6), TIDA-010268_Power Rail (C32.2 C33.1 R54.2)

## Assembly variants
5-7s Battery Pack Design: not fitted FID1 FID2 FID3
